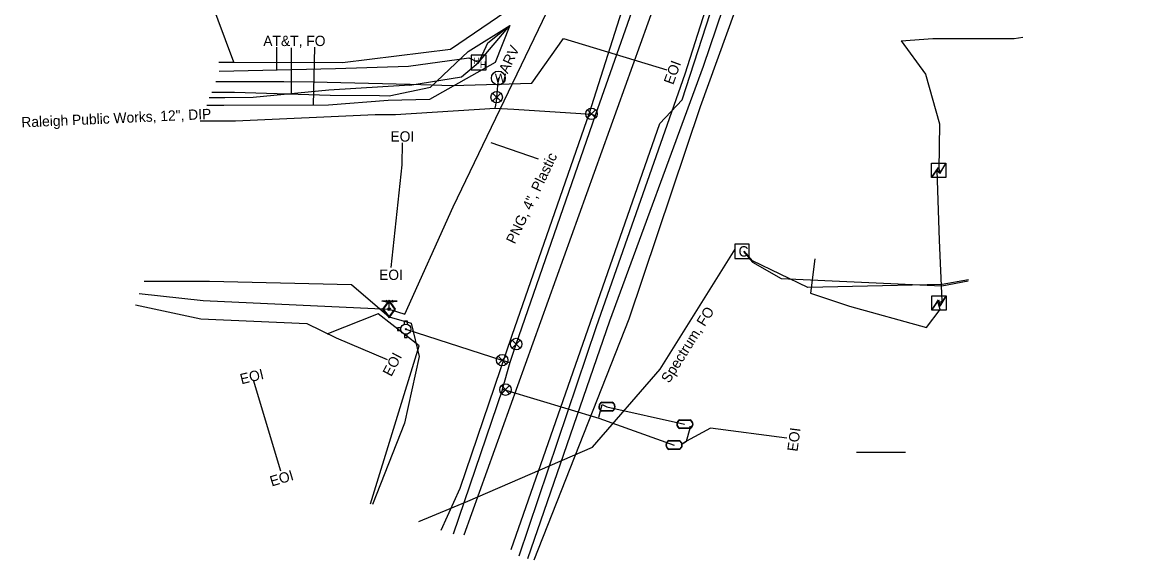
# Model space of a CAD drawing. Extents: x 2070721 to 2083340, y 729290 to 737883.
# Drawn here: x 2080782.3 to 2081212.7, y 732787 to 732995.1 of the extents above; entities that cross this region are included whole.
import ezdxf

# ---------------------------------------------------------------- set-up
doc = ezdxf.new("R2010")
doc.units = 0
for name, color, linetype in [('Exist Utilities Gas Change of Service SUE CELL', 7, 'Continuous'), ('Exist Utilities Gas UG Line SUE LOS B', 7, 'Continuous'), ('Exist Utilities Gas UG Line SUE LOS B Leader', 7, 'Continuous'), ('Exist Utilities Gas UG Line SUE LOS B Text', 7, 'Continuous'), ('Exist Utilities Gas UG Line SUE LOS C', 7, 'Continuous'), ('Exist Utilities Gas Valve CELL', 7, 'Continuous'), ('Exist Utilities Other Pole Text', 7, 'Continuous'), ('Exist Utilities Other Unknown UG SUE LOS B', 7, 'Continuous'), ('Exist Utilities Power Pole Text', 7, 'Continuous'), ('Exist Utilities Power Transformer CELL', 7, 'Continuous'), ('Exist Utilities Power UG Cable SUE LOS B', 7, 'Continuous'), ('Exist Utilities Telephone Hand Hole CELL', 7, 'Continuous'), ('Exist Utilities Telephone UG Cable SUE LOS C', 7, 'Continuous'), ('Exist Utilities Telephone UG FO SUE LOS B', 7, 'Continuous'), ('Exist Utilities Telephone UG FO SUE LOS B Leader', 7, 'Continuous'), ('Exist Utilities Telephone UG FO SUE LOS B Text', 7, 'Continuous'), ('Exist Utilities Telephone UG FO SUE LOS C', 7, 'Continuous'), ('Exist Utilities Telephone UG FO SUE LOS C Leader', 7, 'Continuous'), ('Exist Utilities TV Pedestal CELL', 7, 'Continuous'), ('Exist Utilities TV UG Cable SUE LOS B', 7, 'Continuous'), ('Exist Utilities TV UG Cable SUE LOS C', 7, 'Continuous'), ('Exist Utilities TV UG FO Cable SUE LOS B', 7, 'Continuous'), ('Exist Utilities TV UG FO Cable SUE LOS B Text', 7, 'Continuous'), ('Exist Utilities Water Fire Hydrant CELL', 7, 'Continuous'), ('Exist Utilities Water Manhole CELL', 7, 'Continuous'), ('Exist Utilities Water Manhole Text', 7, 'Continuous'), ('Exist Utilities Water Meter CELL', 7, 'Continuous'), ('Exist Utilities Water UG Line SUE LOS B', 7, 'Continuous'), ('Exist Utilities Water UG Line SUE LOS B Text', 7, 'Continuous'), ('Exist Utilities Water Valve CELL', 7, 'Continuous')]:
    doc.layers.add(name, color=color, linetype=linetype)

msp = doc.modelspace()

# ---------------------------------------------------------------- linework, layer by layer
at = {"layer": 'Exist Utilities Gas Change of Service SUE CELL'}
for p, q in [((2080927.31, 732887.13), (2080921.34, 732887.13)), ((2080924.17, 732884.04), (2080924.17, 732887.13)), ((2080924.17, 732887.13), (2080927.31, 732887.13)), ((2080924.17, 732884.04), (2080924.17, 732884.04))]:
    msp.add_line(p, q, dxfattribs=at)
for points in [[(2080921.34, 732887.13), (2080923.32, 732887.47), (2080922.9, 732887.13), (2080923.28, 732886.82)], [(2080927.31, 732887.13), (2080925.34, 732886.78), (2080925.76, 732887.13), (2080925.37, 732887.43)]]:
    msp.add_lwpolyline(points, close=True, dxfattribs=at)
msp.add_circle((2080924.17, 732884.04), 0.517, dxfattribs=at)
at = {"layer": 'Exist Utilities Gas UG Line SUE LOS B'}
msp.add_lwpolyline([(2080924.17, 732884.04), (2080930.33, 732882.17), (2080949.02, 732923.62), (2080986.84, 733002.49), (2081018.88, 733098.52), (2081046.79, 733177.28), (2081082.41, 733256.43), (2081124.09, 733353.56), (2081157.6, 733423.49)], dxfattribs=at)
at = {"layer": 'Exist Utilities Gas UG Line SUE LOS B Leader'}
msp.add_line((2080963.56, 732948.59), (2080981.81, 732942.29), dxfattribs=at)
at = {"layer": 'Exist Utilities Gas UG Line SUE LOS C'}
msp.add_lwpolyline([(2080827.48, 732890.09), (2080852.24, 732887.36), (2080924.15, 732884.11)], dxfattribs=at)
at = {"layer": 'Exist Utilities Gas Valve CELL'}
msp.add_line((2080924.15, 732884.11), (2080924.15, 732884.11), dxfattribs=at)
msp.add_lwpolyline([(2080924.15, 732887.52), (2080921.61, 732884.11), (2080924.15, 732880.7), (2080926.69, 732884.11), (2080924.15, 732887.52)], dxfattribs=at)
msp.add_lwpolyline([(2080926.44, 732884.11), (2080924.15, 732887.19), (2080921.86, 732884.11), (2080924.15, 732881.03)], close=True, dxfattribs=at)
at = {"layer": 'Exist Utilities Other Unknown UG SUE LOS B'}
for points in [[(2080857.11, 732972.23), (2080883.47, 732972.23), (2080894.81, 732972.11), (2080932.38, 732971.19), (2080948.75, 732970.59), (2080979.46, 732971.61), (2080991.68, 732988.84), (2081031.68, 732976.69)], [(2080929.29, 732948.39), (2080929.09, 732939.96), (2080924.86, 732900.17)], [(2080826.03, 732885.74), (2080851.32, 732880.36), (2080892.32, 732878.51), (2080903.75, 732872.9), (2080923.44, 732864.52)], [(2080882.35, 732821.33), (2080871.74, 732856.59)]]:
    msp.add_lwpolyline(points, dxfattribs=at)
at = {"layer": 'Exist Utilities Power Transformer CELL'}
for p, q in [((2081136.91, 732937.96), (2081136.91, 732937.96)), ((2081137, 732886.66), (2081137, 732886.66))]:
    msp.add_line(p, q, dxfattribs=at)
for points in [[(2081134.06, 732940.57), (2081139.61, 732940.57), (2081139.61, 732935.02), (2081134.06, 732935.02)], [(2081134.16, 732889.27), (2081139.71, 732889.27), (2081139.71, 732883.72), (2081134.16, 732883.72)]]:
    msp.add_lwpolyline(points, close=True, dxfattribs=at)
for points in [[(2081134.06, 732935.02), (2081136.71, 732938.96), (2081137.34, 732936.75), (2081139.61, 732940.57)], [(2081134.13, 732935.02), (2081136.71, 732938.75), (2081137.29, 732936.57), (2081139.61, 732940.42)], [(2081134.16, 732883.72), (2081136.8, 732887.66), (2081137.43, 732885.45), (2081139.71, 732889.27)], [(2081134.23, 732883.72), (2081136.8, 732887.45), (2081137.39, 732885.27), (2081139.71, 732889.12)]]:
    msp.add_lwpolyline(points, dxfattribs=at)
at = {"layer": 'Exist Utilities Power UG Cable SUE LOS B'}
msp.add_line((2081123.97, 732828.63), (2081104.97, 732828.59), dxfattribs=at)
for points in [[(2080924.24, 732966.67), (2080940.22, 732970), (2080954.73, 732983.78), (2080970.95, 732993.82)], [(2081122.3, 732987.96), (2081134.51, 732988.79), (2081149.63, 732988.79), (2081165.98, 732988.79), (2081169.37, 732989.33)], [(2081122.3, 732987.96), (2081131.78, 732974.98), (2081137.18, 732955.83), (2081136.91, 732937.96)], [(2080855.55, 732968), (2080864.32, 732968), (2080901.38, 732966.85), (2080920.52, 732966.81), (2080924.24, 732966.67)], [(2081088.9, 732903.55), (2081087.25, 732890.31), (2081102.37, 732885.27), (2081132.05, 732876.97), (2081137.39, 732883.98), (2081136.65, 732886.55), (2081138.2, 732887.18), (2081137.19, 732910.83), (2081136.21, 732937.71), (2081137.11, 732936.68)], [(2080917.03, 732808.65), (2080935.8, 732869.83), (2080919.99, 732882.22), (2080900.14, 732874.41)], [(2081037.14, 732831.71), (2081039.26, 732832.94), (2081040.66, 732838.05), (2081040.66, 732838.79)], [(2081078.04, 732834.13), (2081048.56, 732837.93), (2081039.26, 732832.93), (2081037.16, 732831.49)]]:
    msp.add_lwpolyline(points, dxfattribs=at)
at = {"layer": 'Exist Utilities Telephone Hand Hole CELL'}
for p, q in [((2080955.99, 732982.39), (2080955.99, 732976.67)), ((2080961.71, 732982.39), (2080955.99, 732982.39)), ((2080961.71, 732976.67), (2080961.71, 732982.39)), ((2080955.99, 732976.67), (2080961.71, 732976.67)), ((2080958.85, 732979.53), (2080958.85, 732979.53))]:
    msp.add_line(p, q, dxfattribs=at)
at = {"layer": 'Exist Utilities Telephone UG Cable SUE LOS C'}
for points in [[(2080953.21, 732796.69), (2081054.09, 733077.62), (2081111.09, 733245.57), (2081176.08, 733423.78), (2081231.97, 733580.28), (2081320.16, 733847.08), (2081418.84, 734093.09), (2081467.34, 734224.03), (2081494.06, 734287.2), (2081526.74, 734352.01), (2081556, 734404.62), (2081808.13, 734757.73), (2081845.73, 734804.26), (2081874.67, 734821.58), (2081898.66, 734810.94), (2081917.15, 734795.51)], [(2080971.45, 732791.05), (2081028.93, 732955.93), (2081037.58, 732965.12), (2081059.34, 733032.5), (2081099.5, 733145.5), (2081127.24, 733222.27), (2081165.53, 733329.08), (2081197.08, 733415.76), (2081225.51, 733493.81), (2081252.34, 733568.18), (2081252.65, 733568.73)], [(2080977.85, 732787.5), (2081009.55, 732879.6), (2081045.87, 732978.13), (2081063.56, 733030.35), (2081103.18, 733143.81), (2081131.57, 733220.23), (2081172.06, 733327.38), (2081203.1, 733413.05), (2081232.13, 733491.49), (2081257.07, 733565.11), (2081257.51, 733566.68)], [(2080980.31, 732787.04), (2081017.13, 732880.26), (2081044.65, 732962.53), (2081058.02, 732999.54), (2081069.26, 733036.84), (2081073.31, 733048.09), (2081079.75, 733057.99), (2081085.51, 733069.49), (2081110.84, 733140.06), (2081139.9, 733217.95), (2081177.19, 733322.59), (2081208.97, 733410.75), (2081237.5, 733489.4), (2081264.77, 733561.01)], [(2080944.31, 732798.44), (2080951.65, 732814.71), (2080971.81, 732874.01), (2081001.7, 732960.05), (2081020.52, 733019.4), (2081051.78, 733107.87), (2081085.75, 733202.6), (2081111.57, 733279.04), (2081128.94, 733334.77), (2081148.26, 733379.04), (2081175.1, 733448.52), (2081180.53, 733478.86)]]:
    msp.add_lwpolyline(points, dxfattribs=at)
at = {"layer": 'Exist Utilities Telephone UG FO SUE LOS B'}
for points in [[(2080974.54, 732788.58), (2081004.48, 732877.32), (2081038.77, 732975.1), (2081057.5, 733033.86), (2081097.09, 733146.25), (2081124.3, 733222.73), (2081163.35, 733330.31), (2081194.31, 733416.96), (2081222.79, 733494.92), (2081247.13, 733564.12), (2081248.81, 733567.64)], [(2080970.95, 732993.82), (2080965.18, 732979.6), (2080939.85, 732965.21), (2080923.77, 732964.8), (2080900.75, 732963)], [(2080932.27, 732970.74), (2080952.25, 732974.02), (2080958.82, 732979.51), (2080970.96, 732993.81)], [(2080958.85, 732979.53), (2080962.37, 732987.19), (2080970.68, 732993.79)], [(2080958.85, 732979.53), (2080962.37, 732987.19), (2080970.68, 732993.79)], [(2080858.5, 732976.22), (2080903.44, 732977.24), (2080931.69, 732978.16), (2080955.04, 732981.38), (2080958.85, 732979.53)], [(2080932.27, 732970.74), (2080900.87, 732968.8), (2080871.59, 732966.01), (2080860.69, 732965.93), (2080854.53, 732965.93)], [(2080900.75, 732963), (2080860.26, 732962.85), (2080853.71, 732962.85)], [(2080900.75, 732963), (2080860.26, 732962.85), (2080853.71, 732962.85)]]:
    msp.add_lwpolyline(points, dxfattribs=at)
at = {"layer": 'Exist Utilities Telephone UG FO SUE LOS B Leader'}
for p, q in [((2080880.72, 732976.79), (2080880.72, 732985.51)), ((2080886.46, 732967.46), (2080886.46, 732985.19)), ((2080894.89, 732963.09), (2080895.51, 732985.5))]:
    msp.add_line(p, q, dxfattribs=at)
at = {"layer": 'Exist Utilities Telephone UG FO SUE LOS C'}
msp.add_lwpolyline([(2080858.37, 732979.69), (2080864.15, 732979.69), (2080906.18, 732979.56), (2080947.92, 732984.72), (2080969.41, 732999.27), (2080978.07, 733014.44)], dxfattribs=at)
at = {"layer": 'Exist Utilities Telephone UG FO SUE LOS C Leader'}
msp.add_line((2080864.15, 732979.69), (2080845.85, 733029.15), dxfattribs=at)
at = {"layer": 'Exist Utilities TV Pedestal CELL'}
msp.add_line((2081060.69, 732906.43), (2081060.69, 732906.43), dxfattribs=at)
msp.add_lwpolyline([(2081057.92, 732903.65), (2081063.47, 732903.65), (2081063.47, 732909.2), (2081057.92, 732909.2), (2081057.92, 732903.65)], dxfattribs=at)
at = {"layer": 'Exist Utilities TV UG Cable SUE LOS B'}
msp.add_lwpolyline([(2081148.4, 732895.44), (2081138.13, 732893.6), (2081086.19, 732892.4), (2081064.85, 732902.78), (2081061.5, 732906.51)], dxfattribs=at)
at = {"layer": 'Exist Utilities TV UG Cable SUE LOS C'}
msp.add_lwpolyline([(2080829.41, 732894.84), (2080854.76, 732894.84), (2080909.66, 732893.59), (2080924.17, 732881.11), (2080932.75, 732878.63), (2080935.76, 732865.71), (2080930.15, 732839.98), (2080917.79, 732808.38)], dxfattribs=at)
at = {"layer": 'Exist Utilities TV UG FO Cable SUE LOS B'}
for points in [[(2080935.73, 732801.82), (2080954.6, 732809.74), (2081002.83, 732830.64), (2081029.04, 732860.86), (2081058.1, 732907.32)], [(2081061.28, 732906.35), (2081064.79, 732902.23), (2081075.86, 732895.9), (2081138.1, 732893.11), (2081148.25, 732895.04)]]:
    msp.add_lwpolyline(points, dxfattribs=at)
at = {"layer": 'Exist Utilities Water Fire Hydrant CELL'}
msp.add_line((2080930.67, 732876.3), (2080930.67, 732876.3), dxfattribs=at)
for points in [[(2080928.75, 732876.81), (2080927.47, 732876.81), (2080927.47, 732875.78), (2080928.75, 732875.78)], [(2080930.15, 732878.21), (2080930.15, 732879.5), (2080931.18, 732879.5), (2080931.18, 732878.18)], [(2080930.15, 732874.38), (2080930.15, 732873.1), (2080931.18, 732873.1), (2080931.18, 732874.41)]]:
    msp.add_lwpolyline(points, dxfattribs=at)
for radius in [1.98, 0.243]:
    msp.add_circle((2080930.67, 732876.3), radius, dxfattribs=at)
at = {"layer": 'Exist Utilities Water Manhole CELL'}
msp.add_line((2080966.45, 732973.52), (2080966.45, 732973.52), dxfattribs=at)
msp.add_circle((2080966.45, 732973.52), 2.69, dxfattribs=at)
at = {"layer": 'Exist Utilities Water Meter CELL'}
for p, q in [((2081008.49, 732846.29), (2081008.49, 732846.29)), ((2081038.62, 732839.51), (2081038.62, 732839.51)), ((2081034.46, 732831.47), (2081034.46, 732831.47))]:
    msp.add_line(p, q, dxfattribs=at)
for points in [[(2081006.45, 732847.99), (2081010.53, 732847.99)], [(2081006.45, 732847.86), (2081010.53, 732847.86)], [(2081010.53, 732844.73), (2081006.43, 732844.73)], [(2081010.53, 732844.59), (2081006.43, 732844.59)], [(2081040.65, 732837.95), (2081036.55, 732837.95)], [(2081036.58, 732841.21), (2081040.65, 732841.21)], [(2081036.58, 732841.08), (2081040.65, 732841.08)], [(2081040.65, 732837.81), (2081036.55, 732837.81)], [(2081036.49, 732829.91), (2081032.39, 732829.91)], [(2081036.49, 732829.77), (2081032.39, 732829.77)], [(2081032.42, 732833.17), (2081036.49, 732833.17)], [(2081032.42, 732833.04), (2081036.49, 732833.04)]]:
    msp.add_lwpolyline(points, dxfattribs=at)
for centre, radius, start, end in [((2081007.18, 732846.29), 1.86, 113.178, 245.9794), ((2081007.19, 732846.29), 1.73, 115.3009, 243.7824), ((2081009.78, 732846.3), 1.86, 293.6483, 66.3084), ((2081009.79, 732846.29), 1.73, 295.1272, 64.8728), ((2081037.31, 732839.51), 1.86, 113.178, 245.9794), ((2081037.32, 732839.51), 1.73, 115.3009, 243.7824), ((2081039.91, 732839.51), 1.86, 293.6483, 66.3084), ((2081039.92, 732839.51), 1.73, 295.1272, 64.8728), ((2081033.15, 732831.47), 1.86, 113.178, 245.9794), ((2081033.16, 732831.47), 1.73, 115.3009, 243.7824), ((2081035.75, 732831.47), 1.86, 293.6483, 66.3084), ((2081035.76, 732831.47), 1.73, 295.1272, 64.8728)]:
    msp.add_arc(centre, radius, start, end, dxfattribs=at)
at = {"layer": 'Exist Utilities Water UG Line SUE LOS B'}
msp.add_line((2080968.02, 732853.09), (2080948.97, 732796.99), dxfattribs=at)
for points in [[(2080968.02, 732853.09), (2080971.09, 732863.55), (2080973.36, 732870.49), (2081004.03, 732959.14), (2081024.87, 733018.36), (2081055.27, 733107.45), (2081086.77, 733195.01), (2081116.19, 733277.07), (2081135.71, 733336.57)], [(2080965.26, 732961.85), (2080965.45, 732963.02), (2080966.01, 732966.32), (2080965.9, 732966.11), (2080966.57, 732973.55)], [(2080851.13, 732956.94), (2080864.81, 732956.94), (2080918.79, 732959.37)], [(2080918.79, 732959.37), (2080926.6, 732959.45), (2080965.26, 732961.85)], [(2080965.26, 732961.85), (2080972.41, 732961.54), (2081002.32, 732959.56), (2081003.97, 732959.21), (2081003.97, 732959.21)], [(2080930.66, 732876.36), (2080967.82, 732864.3), (2080970.98, 732863.37)], [(2080968.03, 732853.13), (2080969.29, 732852.76), (2081005.38, 732841.9), (2081034.46, 732831.44)], [(2081005.33, 732842.26), (2081006.62, 732847.09), (2081008.47, 732846.29), (2081038.51, 732839.48)]]:
    msp.add_lwpolyline(points, dxfattribs=at)
at = {"layer": 'Exist Utilities Water Valve CELL'}
for points in [[(2080967.38, 732967.73), (2080964.23, 732964.58), (2080965.8, 732966.15), (2080967.38, 732964.58), (2080964.23, 732967.73)], [(2081004.07, 732961.26), (2081000.92, 732958.11), (2081002.49, 732959.68), (2081004.07, 732958.11), (2081000.92, 732961.26)], [(2080974.93, 732872.11), (2080971.78, 732868.96), (2080973.35, 732870.54), (2080974.93, 732868.96), (2080971.78, 732872.11)], [(2080969.51, 732865.91), (2080966.36, 732862.76), (2080967.94, 732864.33), (2080969.51, 732862.76), (2080966.36, 732865.91)], [(2080970.81, 732854.48), (2080967.66, 732851.33), (2080969.23, 732852.91), (2080970.81, 732851.33), (2080967.66, 732854.48)]]:
    msp.add_lwpolyline(points, dxfattribs=at)
for centre in [(2080965.8, 732966.15), (2081002.49, 732959.68), (2080973.35, 732870.54), (2080967.94, 732864.33), (2080969.23, 732852.91)]:
    msp.add_circle(centre, 2.23, dxfattribs=at)

# ---------------------------------------------------------------- texts
at = {"layer": 'Exist Utilities Gas UG Line SUE LOS B Text'}
msp.add_text('PNG, 4", Plastic', height=4, rotation=64.3748, dxfattribs=at).set_placement((2080972.85, 732908.99))
at = {"layer": 'Exist Utilities Other Pole Text'}
for rotation, p in [(69.9399, (2081034.08, 732970.69)), (82.6019, (2081082.19, 732828.78))]:
    msp.add_text('EOI', height=4, rotation=rotation, dxfattribs=at).set_placement(p)
at = {"layer": 'Exist Utilities Power Pole Text'}
for p in [(2080924.72, 732948.92), (2080920.32, 732895.36)]:
    msp.add_text('EOI', height=4, dxfattribs=at).set_placement(p)
for rotation, p in [(62.1978, (2080925.03, 732857.69)), (13.7971, (2080867.07, 732854.94)), (16.7177, (2080878.77, 732815.37))]:
    msp.add_text('EOI', height=4, rotation=rotation, dxfattribs=at).set_placement(p)
at = {"layer": 'Exist Utilities Telephone Hand Hole CELL'}
for p in [(2080956.76, 732978.94), (2080959.34, 732977.47)]:
    msp.add_text('H', height=2.5, dxfattribs=at).set_placement(p)
at = {"layer": 'Exist Utilities Telephone UG FO SUE LOS B Text'}
msp.add_text('AT&T, FO', height=4, dxfattribs=at).set_placement((2080875.51, 732985.91))
at = {"layer": 'Exist Utilities TV Pedestal CELL'}
msp.add_text('C', height=4, dxfattribs=at).set_placement((2081059.39, 732904.43))
at = {"layer": 'Exist Utilities TV UG FO Cable SUE LOS B Text'}
msp.add_text('Spectrum, FO', height=4, rotation=57.9806, dxfattribs=at).set_placement((2081032.55, 732855.14))
at = {"layer": 'Exist Utilities Water Manhole CELL'}
msp.add_text('W', height=3.5, dxfattribs=at).set_placement((2080965.1, 732971.77))
at = {"layer": 'Exist Utilities Water Manhole Text'}
msp.add_text('ARV', height=4, rotation=64.6909, dxfattribs=at).set_placement((2080970.06, 732974.98))
at = {"layer": 'Exist Utilities Water UG Line SUE LOS B Text'}
msp.add_text('Raleigh Public Works, 12", DIP', height=4, rotation=2.5774, dxfattribs=at).set_placement((2080781.99, 732954.39))

doc.saveas('drawing.dxf')
